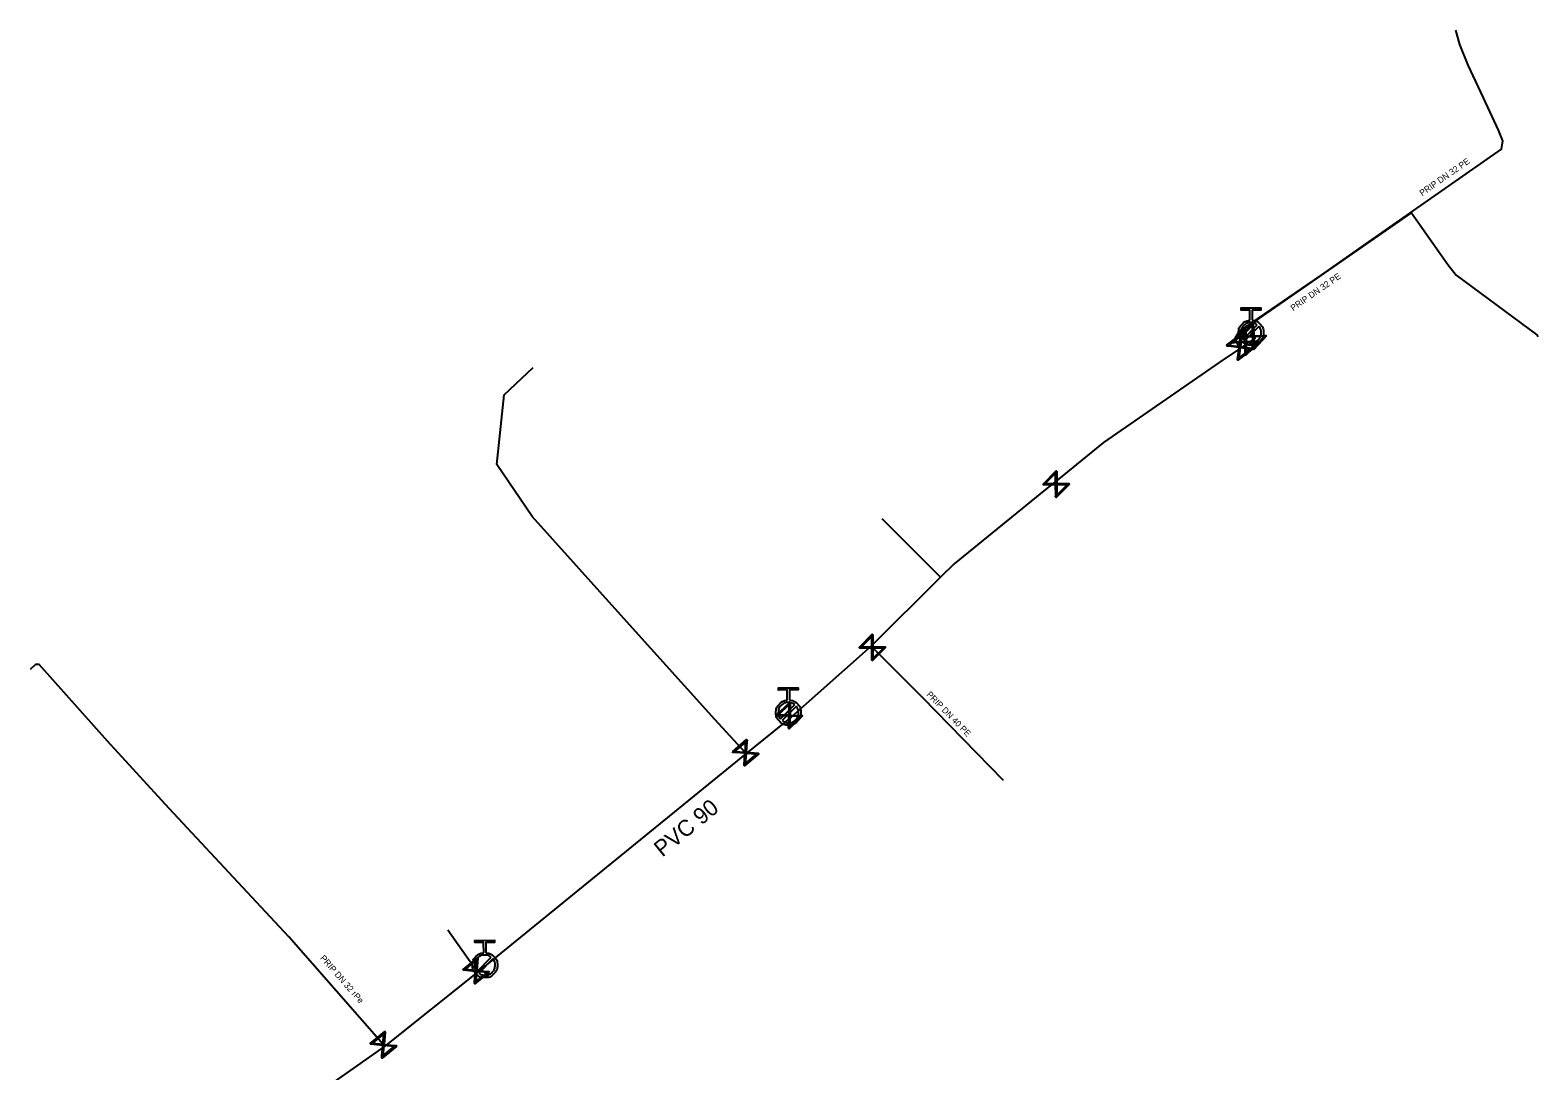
# Model space of a CAD drawing. Extents: x -641905 to -641246, y -1111750 to -1110210.
# Drawn here: x -641366.9 to -641245.9, y -1110471.2 to -1110387.8 of the extents above; entities that cross this region are included whole.
import ezdxf

# ---------------------------------------------------------------- set-up
doc = ezdxf.new("R2010")
doc.units = 0
for name, color, linetype in [('Default', 7, 'Continuous'), ('VP Hydrant', 7, 'Continuous'), ('VP Popis přípojky', 7, 'Continuous'), ('VP Přípojka', 7, 'Continuous'), ('VP Řad', 7, 'Continuous'), ('VP Řad - popis', 7, 'Continuous'), ('VP Šoupě', 7, 'Continuous')]:
    doc.layers.add(name, color=color, linetype=linetype)

msp = doc.modelspace()

# ---------------------------------------------------------------- linework, layer by layer
at = {"layer": 'Default'}
for points in [[(-641268.83, -1110411.04), (-641268.47, -1110411.07), (-641268.21, -1110411.33), (-641267.92, -1110411.62), (-641267.92, -1110412.04), (-641267.92, -1110412.45), (-641268.21, -1110412.74), (-641268.51, -1110413.04), (-641268.92, -1110413.04), (-641269.34, -1110413.04), (-641269.63, -1110412.75), (-641269.92, -1110412.45), (-641269.92, -1110412.04), (-641269.92, -1110411.62), (-641269.63, -1110411.33), (-641269.37, -1110411.07), (-641269.02, -1110411.04)], [(-641268.42, -1110411.4), (-641268.63, -1110411.22), (-641268.93, -1110411.22), (-641269.26, -1110411.22), (-641269.5, -1110411.46), (-641269.74, -1110411.7), (-641269.74, -1110412.04), (-641269.74, -1110412.33), (-641269.56, -1110412.55)], [(-641269.43, -1110412.67), (-641269.21, -1110412.85), (-641268.92, -1110412.85), (-641268.59, -1110412.85), (-641268.35, -1110412.61), (-641268.11, -1110412.37), (-641268.11, -1110412.03), (-641268.11, -1110411.74), (-641268.29, -1110411.53)], [(-641305.95, -1110441.5), (-641305.59, -1110441.53), (-641305.33, -1110441.79), (-641305.04, -1110442.08), (-641305.04, -1110442.5), (-641305.04, -1110442.91), (-641305.33, -1110443.21), (-641305.62, -1110443.5), (-641306.04, -1110443.5), (-641306.45, -1110443.5), (-641306.74, -1110443.21), (-641307.04, -1110442.92), (-641307.04, -1110442.51), (-641307.04, -1110442.09), (-641306.75, -1110441.8), (-641306.49, -1110441.53), (-641306.13, -1110441.5)], [(-641305.53, -1110441.86), (-641305.75, -1110441.68), (-641306.04, -1110441.69), (-641306.38, -1110441.69), (-641306.62, -1110441.92), (-641306.85, -1110442.16), (-641306.85, -1110442.5), (-641306.85, -1110442.79), (-641306.67, -1110443.01)], [(-641306.54, -1110443.14), (-641306.33, -1110443.31), (-641306.04, -1110443.31), (-641305.7, -1110443.31), (-641305.46, -1110443.07), (-641305.23, -1110442.83), (-641305.23, -1110442.5), (-641305.23, -1110442.21), (-641305.4, -1110441.99)], [(-641330.31, -1110461.75), (-641329.95, -1110461.78), (-641329.69, -1110462.04), (-641329.39, -1110462.33), (-641329.39, -1110462.74), (-641329.39, -1110463.16), (-641329.68, -1110463.45), (-641329.97, -1110463.75), (-641330.38, -1110463.75), (-641330.8, -1110463.75), (-641331.09, -1110463.46), (-641331.39, -1110463.17), (-641331.39, -1110462.76), (-641331.39, -1110462.34), (-641331.1, -1110462.05), (-641330.85, -1110461.78), (-641330.49, -1110461.75)], [(-641329.89, -1110462.11), (-641330.11, -1110461.93), (-641330.4, -1110461.94), (-641330.74, -1110461.94), (-641330.97, -1110462.18), (-641331.21, -1110462.42), (-641331.2, -1110462.75), (-641331.2, -1110463.05), (-641331.02, -1110463.26)], [(-641330.89, -1110463.39), (-641330.67, -1110463.56), (-641330.38, -1110463.56), (-641330.05, -1110463.56), (-641329.81, -1110463.32), (-641329.58, -1110463.08), (-641329.58, -1110462.74), (-641329.58, -1110462.45), (-641329.76, -1110462.24)]]:
    msp.add_open_spline(points, degree=3, dxfattribs=at)
at = {"layer": 'VP Hydrant'}
for points in [[(-641269.02, -1110411.04), (-641269.02, -1110410.22), (-641269.71, -1110410.22), (-641269.71, -1110410.04), (-641268.14, -1110410.04), (-641268.14, -1110410.22), (-641268.83, -1110410.22), (-641268.83, -1110411.04)], [(-641269.56, -1110412.55), (-641268.42, -1110411.4)], [(-641268.29, -1110411.53), (-641269.43, -1110412.67)], [(-641306.13, -1110441.5), (-641306.14, -1110440.68), (-641306.83, -1110440.69), (-641306.83, -1110440.5), (-641305.26, -1110440.5), (-641305.26, -1110440.68), (-641305.95, -1110440.68), (-641305.95, -1110441.5)], [(-641306.67, -1110443.01), (-641305.53, -1110441.86)], [(-641305.4, -1110441.99), (-641306.54, -1110443.14)], [(-641330.49, -1110461.75), (-641330.5, -1110460.93), (-641331.19, -1110460.94), (-641331.19, -1110460.76), (-641329.62, -1110460.74), (-641329.62, -1110460.93), (-641330.31, -1110460.93), (-641330.31, -1110461.75)], [(-641331.02, -1110463.26), (-641329.89, -1110462.11)], [(-641329.76, -1110462.24), (-641330.89, -1110463.39)]]:
    msp.add_lwpolyline(points, dxfattribs=at)
at = {"layer": 'VP Přípojka'}
for points in [[(-641269.78, -1110413.28), (-641269.89, -1110413.11), (-641270.1, -1110412.76), (-641270.17, -1110412.41), (-641269.86, -1110411.91), (-641263.31, -1110407.44), (-641259.75, -1110404.94), (-641256.19, -1110402.44), (-641248.82, -1110397.31), (-641248.73, -1110396.66), (-641249.06, -1110395.81), (-641250.28, -1110393.2), (-641251.5, -1110390.58), (-641252.16, -1110388.92), (-641252.48, -1110387.78)], [(-641269.23, -1110412.9), (-641269.36, -1110412.78), (-641269.93, -1110412.05), (-641256.06, -1110402.42), (-641253.14, -1110406.57), (-641252.46, -1110407.42), (-641246, -1110412.21), (-641245.91, -1110412.38)], [(-641309.42, -1110445.79), (-641309.48, -1110445.72), (-641311.94, -1110443.05), (-641319.49, -1110434.69), (-641326.6, -1110426.77), (-641329.43, -1110422.6), (-641328.85, -1110417.03), (-641326.53, -1110414.83)], [(-641293.83, -1110431.65), (-641298.51, -1110426.97)], [(-641299.41, -1110437.17), (-641295.28, -1110441.28), (-641288.81, -1110447.92)], [(-641338.43, -1110469.25), (-641338.53, -1110469.14), (-641346.13, -1110460.47), (-641355.73, -1110450.19), (-641360.67, -1110444.79), (-641366.15, -1110438.65), (-641366.44, -1110438.63), (-641366.88, -1110439.03)], [(-641306.04, -1110442.5), (-641305.96, -1110442.74), (-641305.81, -1110442.86)], [(-641330.99, -1110463.31), (-641331.08, -1110463.2), (-641333.36, -1110459.95)]]:
    msp.add_lwpolyline(points, dxfattribs=at)
at = {"layer": 'VP Řad'}
msp.add_lwpolyline([(-641268.93, -1110412.03), (-641268.93, -1110412.04), (-641268.75, -1110412.33), (-641268.6, -1110412.47), (-641269.23, -1110412.9), (-641269.78, -1110413.28), (-641271.48, -1110414.44), (-641280.76, -1110420.83), (-641284.67, -1110424.02), (-641285.41, -1110424.61), (-641292.73, -1110430.56), (-641293.83, -1110431.65), (-641299.41, -1110437.17), (-641305.81, -1110442.86), (-641309.42, -1110445.79), (-641330.99, -1110463.31), (-641338.43, -1110469.25), (-641343.44, -1110472.77)], dxfattribs=at)
at = {"layer": 'VP Šoupě'}
for points in [[(-641267.69, -1110412.29), (-641268.71, -1110413.39), (-641268.76, -1110413.34), (-641268.76, -1110413.22), (-641268.79, -1110412.38), (-641269.76, -1110412.41), (-641269.81, -1110412.37), (-641268.79, -1110411.27), (-641268.74, -1110411.31), (-641268.71, -1110412.29), (-641267.87, -1110412.26), (-641267.74, -1110412.25), (-641267.69, -1110412.29)], [(-641269.64, -1110412.32), (-641268.79, -1110412.29), (-641268.82, -1110411.45), (-641269.64, -1110412.32)], [(-641270.88, -1110413.05), (-641269.69, -1110412.14), (-641269.65, -1110412.2), (-641269.67, -1110412.32), (-641269.78, -1110413.16), (-641268.82, -1110413.28), (-641268.78, -1110413.34), (-641269.97, -1110414.25), (-641270.01, -1110414.19), (-641269.88, -1110413.23), (-641270.72, -1110413.12), (-641270.84, -1110413.11), (-641270.88, -1110413.05)], [(-641270.7, -1110413.03), (-641269.87, -1110413.14), (-641269.76, -1110412.31), (-641270.7, -1110413.03)], [(-641270.42, -1110412.81), (-641269.39, -1110411.72), (-641269.34, -1110411.77), (-641269.34, -1110411.89), (-641269.32, -1110412.73), (-641268.35, -1110412.7), (-641268.3, -1110412.75), (-641269.33, -1110413.84), (-641269.38, -1110413.79), (-641269.4, -1110412.82), (-641270.24, -1110412.85), (-641270.37, -1110412.86), (-641270.42, -1110412.81)], [(-641270.24, -1110412.76), (-641269.41, -1110412.74), (-641269.43, -1110411.9), (-641270.24, -1110412.76)], [(-641267.87, -1110412.34), (-641268.7, -1110412.37), (-641268.67, -1110413.21), (-641267.87, -1110412.34)], [(-641268.96, -1110413.35), (-641269.8, -1110413.24), (-641269.91, -1110414.08), (-641268.96, -1110413.35)], [(-641268.47, -1110412.79), (-641269.32, -1110412.82), (-641269.29, -1110413.66), (-641268.47, -1110412.79)], [(-641283.49, -1110424.18), (-641284.55, -1110425.24), (-641284.6, -1110425.2), (-641284.59, -1110425.07), (-641284.6, -1110424.23), (-641285.57, -1110424.23), (-641285.61, -1110424.18), (-641284.55, -1110423.12), (-641284.51, -1110423.17), (-641284.51, -1110424.14), (-641283.67, -1110424.14), (-641283.54, -1110424.14), (-641283.49, -1110424.18)], [(-641285.44, -1110424.14), (-641284.6, -1110424.14), (-641284.6, -1110423.3), (-641285.44, -1110424.14)], [(-641283.67, -1110424.23), (-641284.51, -1110424.23), (-641284.51, -1110425.07), (-641283.67, -1110424.23)], [(-641298.24, -1110437.27), (-641299.3, -1110438.33), (-641299.35, -1110438.29), (-641299.35, -1110438.16), (-641299.35, -1110437.32), (-641300.32, -1110437.32), (-641300.37, -1110437.27), (-641299.31, -1110436.21), (-641299.26, -1110436.26), (-641299.26, -1110437.23), (-641298.42, -1110437.23), (-641298.29, -1110437.22), (-641298.24, -1110437.27)], [(-641300.19, -1110437.23), (-641299.35, -1110437.23), (-641299.35, -1110436.39), (-641300.19, -1110437.23)], [(-641298.42, -1110437.32), (-641299.26, -1110437.32), (-641299.26, -1110438.15), (-641298.42, -1110437.32)], [(-641307.02, -1110442.71), (-641305.93, -1110441.68), (-641305.88, -1110441.73), (-641305.89, -1110441.86), (-641305.91, -1110442.7), (-641304.94, -1110442.73), (-641304.9, -1110442.77), (-641305.99, -1110443.8), (-641306.04, -1110443.75), (-641306.01, -1110442.78), (-641306.84, -1110442.75), (-641306.97, -1110442.75), (-641307.02, -1110442.71)], [(-641306.84, -1110442.67), (-641306, -1110442.69), (-641305.98, -1110441.86), (-641306.84, -1110442.67)], [(-641305.07, -1110442.81), (-641305.92, -1110442.78), (-641305.94, -1110443.62), (-641305.07, -1110442.81)], [(-641310.54, -1110445.64), (-641309.4, -1110444.66), (-641309.36, -1110444.71), (-641309.37, -1110444.84), (-641309.43, -1110445.68), (-641308.47, -1110445.75), (-641308.42, -1110445.8), (-641309.56, -1110446.78), (-641309.6, -1110446.73), (-641309.53, -1110445.76), (-641310.37, -1110445.7), (-641310.49, -1110445.69), (-641310.54, -1110445.64)], [(-641310.36, -1110445.61), (-641309.52, -1110445.67), (-641309.46, -1110444.84), (-641310.36, -1110445.61)], [(-641308.6, -1110445.83), (-641309.44, -1110445.77), (-641309.5, -1110446.6), (-641308.6, -1110445.83)], [(-641330.04, -1110463.31), (-641331.19, -1110464.26), (-641331.24, -1110464.21), (-641331.22, -1110464.08), (-641331.14, -1110463.25), (-641332.11, -1110463.15), (-641332.15, -1110463.1), (-641330.99, -1110462.15), (-641330.95, -1110462.2), (-641331.04, -1110463.17), (-641330.21, -1110463.25), (-641330.08, -1110463.25), (-641330.04, -1110463.31)], [(-641331.97, -1110463.08), (-641331.13, -1110463.16), (-641331.05, -1110462.32), (-641331.97, -1110463.08)], [(-641330.22, -1110463.33), (-641331.05, -1110463.25), (-641331.13, -1110464.09), (-641330.22, -1110463.33)], [(-641337.47, -1110469.24), (-641338.63, -1110470.2), (-641338.67, -1110470.15), (-641338.66, -1110470.02), (-641338.58, -1110469.18), (-641339.54, -1110469.09), (-641339.59, -1110469.04), (-641338.43, -1110468.08), (-641338.39, -1110468.13), (-641338.48, -1110469.1), (-641337.65, -1110469.18), (-641337.52, -1110469.19), (-641337.47, -1110469.24)], [(-641339.41, -1110469.01), (-641338.57, -1110469.09), (-641338.49, -1110468.26), (-641339.41, -1110469.01)], [(-641337.66, -1110469.27), (-641338.49, -1110469.19), (-641338.57, -1110470.02), (-641337.66, -1110469.27)]]:
    msp.add_lwpolyline(points, dxfattribs=at)

# ---------------------------------------------------------------- texts
at = {"layer": 'VP Popis přípojky'}
for s, rotation, p in [('PRIP DN 32 PE', 34.8404, (-641255.19, -1110401.1)), ('PRIP DN 32 PE', 34.7724, (-641265.54, -1110410.32)), ('PRIP DN 40 PE', 314.314, (-641295, -1110441.09)), ('PRIP DN 32 rPe', 311.2373, (-641343.65, -1110462.21))]:
    msp.add_text(s, height=0.5, rotation=rotation, dxfattribs=at).set_placement(p)
at = {"layer": 'VP Řad - popis'}
msp.add_text('PVC 90', height=1.3, rotation=39.2768, dxfattribs=at).set_placement((-641316.16, -1110454.13))

doc.saveas('drawing.dxf')
